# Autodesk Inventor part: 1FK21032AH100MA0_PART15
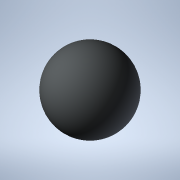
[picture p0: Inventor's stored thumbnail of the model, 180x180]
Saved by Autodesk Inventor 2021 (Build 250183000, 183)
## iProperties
Created: 2025-04
Part Number: 1FK21032AH100MA0_PART15
Material: Generic
Catalog Web Link: www.3dfindit.com
Description: -Servo synchronous motor
Document SubType Name: Modeling
Designer: psAdmin
Mass: 0.113097 g
Surface Area: 1.13097 cm^2
Volume: 0.113097 cm^3
Density: 1 g/cm^3
Appearance: PSOLRGB-212-217-219
Category: PARTsolutions
Title: 1FK21032AH100MA0_PART15
Author: Cadenas PARTsolutions
Comments: Servo synchronous motor
Sending System: PARTsolutions
Preprocessor: ST-DEVELOPER v19.3
PSOL_IDENT_0: {$CADENAS_DATA/23d-libs/siemens_ag/_cat_/12/33/1fk21032ah100ma0.prj},216 {VTYP=3D},{NB=1FK21032AH100
PSOL_IDENT_1: MA0_PART15},{LINA=1FK21032AH100MA0_PART15},{NN=1FK21032AH100MA0_PART15},{NOPRJ=TRUE},{DATE=19.08.202
PSOL_IDENT_2: 5 14:00:27},{GEOMDATE=30.07.2025 02:02:58},{VERSION=},{LINEID=10},{WBVAR=},{WBNUMERIC=}  {NB=1FK2103
PSOL_IDENT_3: 2AH100MA0_PART15},{LINA=1FK21032AH100MA0_PART15},{KT=DUMMY},{PREVIEW=../../../_pool_/d3/78/p_d211_xx
PSOL_IDENT_4: _00934j.png},{DESCSHORT=SIMOTICS S-1FK2 HD, SINAMICS S210 3AC 400V-480V, 0.59 Nm, 4500 rpm},{DESCLON
PSOL_IDENT_5: G=SIMOTICS S-1FK2 HD servo motor M0=0.64 Nm; PN = 0.28 kW at nN=4500 rpm (380-480 V); PN = 0.167 kW
PSOL_IDENT_6: at nN=2500 rpm (200-240 V); with holding brake; degree of protection IP64; cylindrical shaft D14 x 3
PSOL_IDENT_7: 0 mm; absolute encoder 22-bit + 12-bit multiturn (encoder AM22DQC); with OCC interface; plug size M1
PSOL_IDENT_8: 7, rotatable; SIMOTICS S-1FK2 servomotorfor a wide range of uses in industrial environments. SIMOTIC
PSOL_IDENT_9: S S‑1FK2 servomotors are compact synchronous motors with a high dynamic performance that set themsel
PSOL_IDENT_10: ves apart as a result of their high power density, degree of protection and overload capability. The
PSOL_IDENT_11: motors are available in two variants: as High Dynamic variant (highest dynamic performance as a res
PSOL_IDENT_12: ult of the low intrinsic moment of inertia for applications demanding a high dynamic performance wit
PSOL_IDENT_13: h low moved masses) - and as Compact variant (precise and stable closed-loop control for medium up t
PSOL_IDENT_14: o large moved masses as a result of a medium intrinsic moment of inertia). SIMOTICSS‑1FK2 servomotor
PSOL_IDENT_15: s fully exploit their strengths in a system with the SINAMICSS210 frequency converter and simple con
PSOL_IDENT_16: nection using the one cable connection (OCC). Advantages include the short control and positioning t
PSOL_IDENT_17: imes, fast and precise correction of disturbing quantities as well as stable control with a high dyn
PSOL_IDENT_18: amic performance. The servo motors can be configured to address a wide range of requirements. For ex
PSOL_IDENT_19: ample with and without holding brake, IP64 or IP65 degree of protection, singleturn or multiturn abs
PSOL_IDENT_20: olute encoders - to name just a few. Further, the servomotors are available in different shaft heigh
PSOL_IDENT_21: ts extending from 20 to 100. A shaft sealing ring is available to achieve an IP65 degree of protecti
PSOL_IDENT_22: on and for subsequent mounting at the motor or as spare part. SIMOTICS - the optimum motor for each
PSOL_IDENT_23: and every motion control application.},{INTNO=195125315563},{SUPPLIERALTNO=1FK2103-2AH10-0MA0},{MANU
PSOL_IDENT_24: ID=1FK21032AH100MA0},{MANUNAME=Siemens},{MANUTYPEDESC=SYNCHRONOUS MOTOR 1FK2 HD 0,64 NM},{AAU732=SIM
PSOL_IDENT_25: OTICS},{AAO057=S-1FK2},{AAU734=SIMOTICS S-1FK2 HD servo motor M0=0.64 Nm; PN = 0.28 kW at nN=4500 rp
PSOL_IDENT_26: m (380-480 V); PN = 0.167 kW at nN=2500 rpm (200-240 V); with holding brake; degree of protection IP
PSOL_IDENT_27: 64; cylindrical shaft D14 x 30 mm; absolute encoder 22-bit + 12-bit multiturn (encoder AM22DQC); wit
PSOL_IDENT_28: h OCC interface; plug size M17, rotatable;},{AAW338=SYNCHRONOUS MOTOR 1FK2 HD 0,64 NM},{AAO742=SIMOT
PSOL_IDENT_29: ICS},{AAO663=4034106444723},{NOCUPEROU=1},{PRICEQUANTITY=1},{QUANTITYMIN=1},{QUANTITYINT=1},{CTN=850
PSOL_IDENT_30: 15100},{COO=RO},{AAO676=1FK2103-2AH10-0MA0},{AAO677=Siemens AG},{ORDERUNIT=C62},{CONTENTUNIT=C62}
NB: 1FK21032AH100MA0_PART15
NT: Servo synchronous motor
NBSYN: $MANUID._PART15
LINA: 1FK21032AH100MA0_PART15
CATALOG: SIEMENS
PREVIEW: ../../../_pool_/d3/78/p_d211_xx_00934j.png
DESCSHORT: SIMOTICS S-1FK2 HD, SINAMICS S210 3AC 400V-480V, 0.59 Nm, 4500 rpm
DESCLONG: SIMOTICS S-1FK2 HD servo motor M0=0.64 Nm; PN = 0.28 kW at nN=4500 rpm (380-480 V); PN = 0.167 kW at nN=2500 rpm (200-240 V); with holding brake; degree of prot
INTNO: 195125315563
SUPPLIERALTNO: 1FK2103-2AH10-0MA0
MANUID: 1FK21032AH100MA0
MANUNAME: Siemens
MANUTYPEDESC: SYNCHRONOUS MOTOR 1FK2 HD 0,64 NM
AAU732: SIMOTICS
AAO057: S-1FK2
AAU734: SIMOTICS S-1FK2 HD servo motor M0=0.64 Nm; PN = 0.28 kW at nN=4500 rpm (380-480 V); PN = 0.167 kW at nN=2500 rpm (200-240 V); with holding brake; degree of prot
AAW338: SYNCHRONOUS MOTOR 1FK2 HD 0,64 NM
AAO742: SIMOTICS
AAO663: 4034106444723.0
NOCUPEROU: 1
PRICEQUANTITY: 1
QUANTITYMIN: 1
QUANTITYINT: 1
CTN: 85015100
COO: RO
ARTICLENO: 1FK21032AH100MA0_PART15
BOMINFO: 1FK21032AH100MA0_PART15
CREATOR: CADENAS GmbH
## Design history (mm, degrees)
feature "2025_04_17_15_06_16_0705"
body "Solid1"
